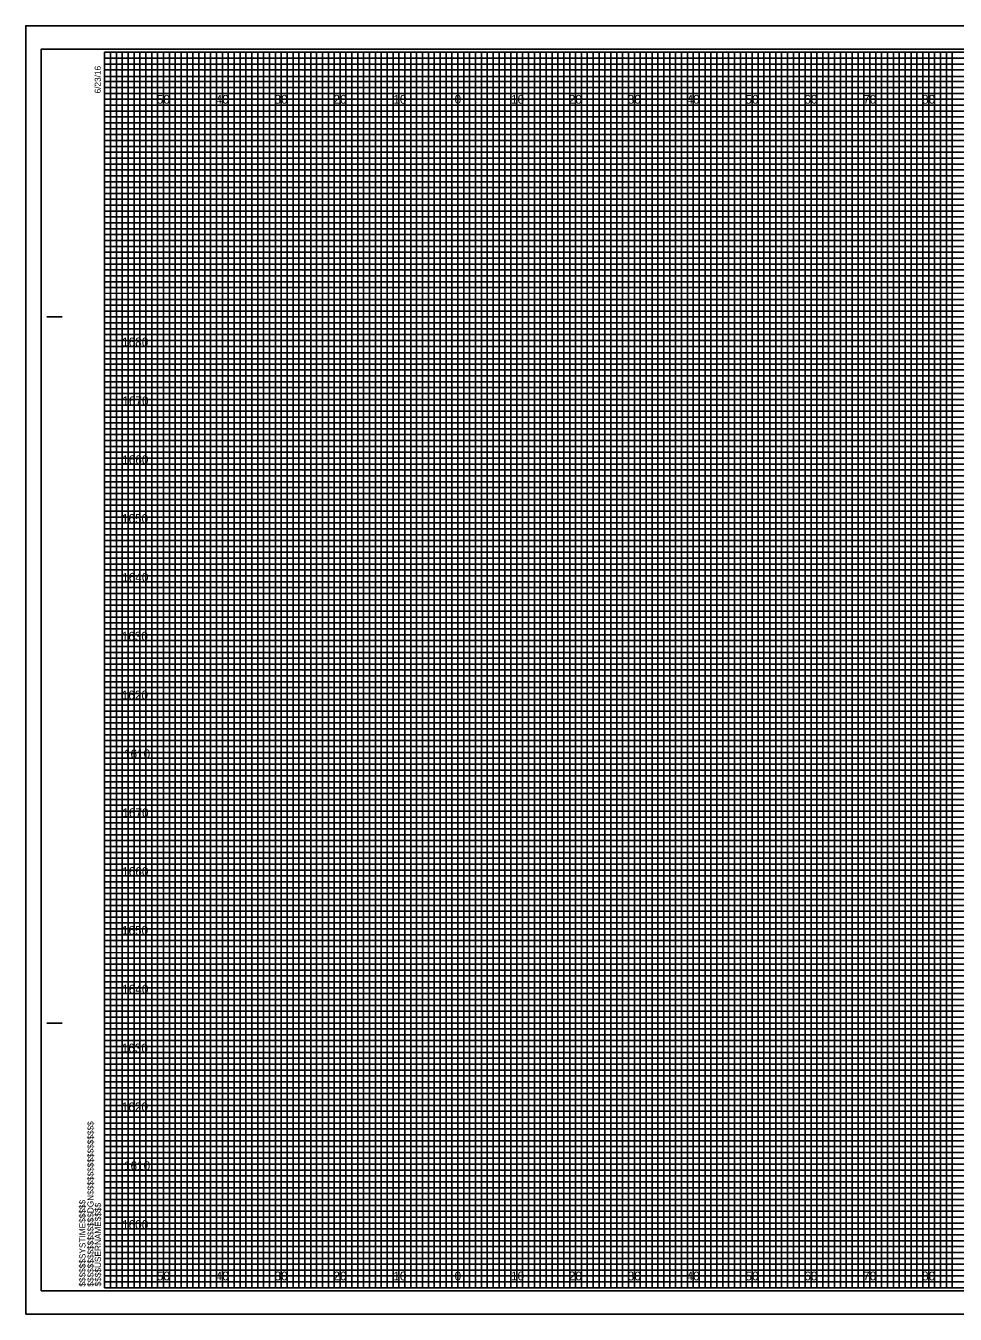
# Model space of a CAD drawing. Extents: x -13 to 323, y -5 to 6154.
# Drawn here: x -13.4 to 144.5, y 4395.5 to 4614.5 of the extents above; entities that cross this region are included whole.
import ezdxf

# ---------------------------------------------------------------- set-up
doc = ezdxf.new("R2010")
doc.units = 0
for name, color, linetype in [('Prop Retaining Wall', 7, 'Continuous'), ('Prop XS Alignment Label', 7, 'Continuous'), ('Prop XS DDE', 7, 'Continuous'), ('Prop XS DDE Elevations', 7, 'Continuous'), ('Prop XS DDE Slope Text', 7, 'Continuous'), ('Prop XS Earthwork Shape', 7, 'Continuous'), ('Prop XS Elevation Labels', 7, 'Continuous'), ('Prop XS Station Labels', 7, 'Continuous'), ('Raster_Level_0', 7, 'Continuous'), ('Scratch_Level_3', 7, 'Continuous'), ('Sheet Cutting Line CELL', 7, 'Continuous')]:
    doc.layers.add(name, color=color, linetype=linetype)

msp = doc.modelspace()

# ---------------------------------------------------------------- linework, layer by layer
at = {"layer": 'Prop Retaining Wall'}
for p, q in [((0, 4609), (260, 4609)), ((260, 4607.98), (0, 4607.98)), ((0, 4607.98), (0, 4607)), ((0, 4607), (260, 4607)), ((260, 4605.89), (0, 4605.89)), ((0, 4605.89), (0, 4604)), ((0, 4604), (320, 4604))]:
    msp.add_line(p, q, dxfattribs=at)
for points in [[(0, 4603), (270, 4603), (320, 4603), (320, 4602), (0, 4602)], [(0, 4601), (320, 4601), (320, 4599), (0, 4599)], [(0, 4598), (320, 4598), (320, 4597), (0, 4596.98)], [(0, 4596), (320, 4596), (320, 4594), (0, 4594)], [(0, 4593), (320, 4593), (320, 4592), (0, 4592)], [(0, 4591), (320, 4591), (320, 4589), (0, 4589)], [(0, 4588), (320, 4588), (320, 4587), (0, 4587)], [(0, 4586), (320, 4586), (320, 4584), (0, 4584)], [(0, 4583), (320, 4583), (320, 4582), (0, 4582)], [(0, 4581), (320, 4581), (320, 4579), (0, 4579)], [(0, 4578), (320, 4578), (320, 4577), (0, 4577)], [(0, 4576), (320, 4576), (320, 4573.95), (320, 4573), (320, 4572), (0, 4572)], [(0, 4574), (320, 4574), (320, 4573), (0, 4573)], [(0, 4571), (320, 4571), (320, 4569), (0, 4569.03)], [(0, 4569.03), (320, 4569), (320, 4568), (0, 4568)], [(0, 4567), (320, 4567), (320, 4566), (0, 4566)], [(0, 4564), (320, 4564), (320, 4563), (0, 4563)], [(0, 4562), (320, 4562), (320, 4561), (0, 4561)], [(-0.07, 4558.89), (320, 4558.89), (320, 4557.88), (-0.07, 4557.88)], [(0, 4557), (320, 4557), (320, 4556), (0, 4556)], [(0, 4554), (320, 4554), (320, 4553), (0, 4553)], [(0, 4552), (320, 4552), (320, 4551), (0, 4551)], [(0, 4549), (320, 4549), (320, 4548), (0, 4548)], [(0, 4547), (320, 4547), (320, 4546), (0, 4546)], [(0, 4544), (320, 4544), (320, 4543), (0, 4543)], [(0, 4542), (320, 4542), (320, 4541), (0, 4541)], [(0, 4539), (320, 4539), (319.99, 4537.98), (0, 4538)], [(0, 4537), (320, 4537), (320, 4536), (0, 4536)], [(0, 4534), (320, 4534), (320, 4533), (0, 4533)], [(0, 4532), (320, 4532), (320, 4531), (0, 4531)], [(0, 4529), (320, 4529), (320, 4528), (0, 4528)], [(0, 4527), (320, 4527), (320, 4526), (0, 4526)], [(0, 4524), (320, 4524), (320, 4523), (0, 4523)], [(0, 4522), (320, 4522), (320, 4521), (0, 4521)], [(0, 4519), (320, 4519), (320, 4518), (0, 4518)], [(0, 4516.99), (320.07, 4516.91), (320, 4516), (0, 4516)], [(0, 4514), (320, 4514), (320, 4513), (0, 4513)], [(0, 4512), (320, 4512), (320, 4511), (0, 4511)], [(0, 4509), (320, 4509), (320, 4508), (0, 4508)], [(0, 4507), (320, 4507), (320, 4506), (0, 4506)], [(0, 4504), (320, 4504), (320, 4503), (0, 4503)], [(0, 4502), (320, 4502), (320, 4501), (0, 4501)], [(0, 4499), (320, 4499), (320, 4498), (0, 4498)], [(0, 4497), (320, 4497), (320, 4496), (0, 4496)], [(0, 4494), (320, 4494), (320, 4493), (0, 4493)], [(0, 4492), (320, 4492), (320, 4491), (0, 4491)], [(0, 4489), (320, 4489), (320, 4488), (0, 4488)], [(0, 4487), (320, 4487), (320, 4486), (0, 4486)], [(0, 4484), (320, 4484), (320, 4483), (0, 4483)], [(0, 4482), (320, 4482), (320, 4481), (0, 4481)], [(0, 4479), (320, 4479), (319.99, 4477.98), (0, 4478)], [(0, 4477), (320, 4477), (320, 4476), (0, 4476)], [(0, 4474), (320, 4474), (320, 4473), (0, 4473)], [(0, 4472), (320, 4472), (320, 4471), (0, 4471)], [(0, 4469), (320, 4469), (320, 4468), (0, 4468)], [(0, 4467), (320, 4467), (320, 4466), (0, 4466)], [(0, 4464), (320, 4464), (320, 4463), (0, 4463)], [(0, 4462), (320, 4462), (320, 4461), (0, 4461)], [(0, 4459), (320, 4459), (320, 4458), (0, 4458)], [(0, 4456.99), (320.07, 4456.91), (320, 4456), (0, 4456)], [(0, 4454), (320, 4454), (320, 4453), (0, 4453)], [(0, 4452), (320, 4452), (320, 4451), (0, 4451)], [(0, 4449), (320, 4449), (320, 4448), (0, 4448)], [(0, 4447), (320, 4447), (320, 4446), (0, 4446)], [(0, 4444), (320, 4444), (320, 4443), (0, 4443)], [(0, 4442), (320, 4442), (320, 4441), (0, 4441)], [(0, 4439), (320, 4439), (320, 4438), (0, 4438)], [(0, 4437), (320, 4437), (320, 4436), (0, 4436)], [(0, 4434), (320, 4434), (320, 4433), (0, 4433)], [(0, 4432), (320, 4432), (320, 4431), (0, 4431)], [(0, 4429), (320, 4429), (320, 4428), (0, 4428)], [(0, 4427), (320, 4427), (320, 4426), (0, 4426)], [(0, 4424), (320, 4424), (320, 4423), (0, 4423)], [(0, 4422), (320, 4422), (320, 4421), (0, 4421)], [(0, 4419), (320, 4419), (320, 4418), (0, 4418)], [(0, 4417), (320, 4417), (320, 4416), (0, 4416)], [(0, 4414), (320, 4414), (320, 4413), (0, 4413)], [(0, 4412), (320, 4412), (320, 4411), (0, 4411)], [(0, 4409), (320, 4409), (320, 4408), (0, 4408)], [(0, 4407), (320, 4407), (320, 4406), (0, 4406)], [(0, 4404), (320, 4404), (320, 4403), (0, 4403)], [(0, 4402), (320, 4402), (320, 4401), (0, 4401)]]:
    msp.add_lwpolyline(points, dxfattribs=at)
at = {"layer": 'Prop XS Alignment Label'}
for p, q in [((-9.8, 4565), (-7.3, 4565)), ((-9.7, 4565), (-7.2, 4565)), ((-9.8, 4445), (-7.3, 4445)), ((-9.7, 4445), (-7.2, 4445)), ((0, 4400), (0, 4400)), ((0, 4400), (0, 4400)), ((0, 4400), (0, 4400)), ((0, 4400), (0, 4400)), ((0, 4400), (0, 4400)), ((0, 4400), (0, 4400)), ((0, 4400), (0, 4400))]:
    msp.add_line(p, q, dxfattribs=at)
msp.add_lwpolyline([(320, 4610), (0, 4610), (0, 4400), (320, 4400)], close=True, dxfattribs=at)
at = {"layer": 'Prop XS DDE'}
msp.add_lwpolyline([(-13.4, 4395.5), (323.3, 4395.5), (323.3, 4614.5), (-13.4, 4614.5)], close=True, dxfattribs=at)
at = {"layer": 'Prop XS DDE Elevations'}
for p, q in [((10, 4400), (10, 4610)), ((20, 4400), (20, 4610)), ((30, 4400), (30, 4610)), ((40, 4400), (40, 4610)), ((50, 4400), (50, 4610)), ((60, 4400), (60, 4610)), ((70, 4400), (70, 4610)), ((80, 4400), (80, 4610)), ((90, 4400), (90, 4610)), ((100, 4400), (100, 4610)), ((110, 4400), (110, 4610)), ((120, 4400), (120, 4610)), ((130, 4400), (130, 4610)), ((140, 4400), (140, 4610)), ((0, 4600), (320, 4600)), ((0, 4590), (320, 4590)), ((0, 4580), (320, 4580)), ((0, 4570), (320, 4570)), ((0, 4560), (320, 4560)), ((0, 4550), (320, 4550)), ((0, 4540), (320, 4540)), ((0, 4530), (320, 4530)), ((0, 4520), (320, 4520)), ((0, 4510), (320, 4510)), ((0, 4500), (320, 4500)), ((0, 4490), (320, 4490)), ((0, 4480), (320, 4480)), ((0, 4470), (320, 4470)), ((0, 4460), (320, 4460)), ((0, 4450), (320, 4450)), ((0, 4440), (320, 4440)), ((0, 4430), (320, 4430)), ((0, 4420), (320, 4420)), ((0, 4410), (320, 4410))]:
    msp.add_line(p, q, dxfattribs=at)
at = {"layer": 'Prop XS DDE Slope Text'}
msp.add_lwpolyline([(-10.8, 4399.5), (322.4, 4399.5), (322.4, 4610.5), (-10.8, 4610.5)], close=True, dxfattribs=at)
at = {"layer": 'Prop XS Earthwork Shape'}
for p, q in [((10, 4610), (0, 4610)), ((10, 4400), (10, 4610)), ((30, 4610), (20, 4610)), ((20, 4610), (20, 4400)), ((30, 4400), (30, 4610)), ((50, 4610), (40, 4610)), ((40, 4610), (40, 4400)), ((50, 4400), (50, 4610)), ((70, 4610), (60, 4610)), ((60, 4610), (60, 4400)), ((70, 4400), (70, 4610)), ((90, 4610), (80, 4610)), ((80, 4610), (80, 4400)), ((90, 4400), (90, 4610)), ((110, 4610), (100, 4610)), ((100, 4610), (100, 4400)), ((110, 4400), (110, 4610)), ((130, 4610), (120, 4610)), ((120, 4610), (120, 4400)), ((130, 4400), (130, 4610)), ((150, 4610), (140, 4610)), ((140, 4610), (140, 4400)), ((20, 4400), (10, 4400)), ((40, 4400), (30, 4400)), ((60, 4400), (50, 4400)), ((80, 4400), (70, 4400)), ((100, 4400), (90, 4400)), ((120, 4400), (110, 4400)), ((140, 4400), (130, 4400))]:
    msp.add_line(p, q, dxfattribs=at)
for points in [[(0, 4600), (320, 4600), (320, 4590), (0, 4590)], [(0, 4580), (320, 4580), (320, 4570), (0, 4570)], [(0, 4560), (320, 4560), (320, 4550), (0, 4550)], [(0, 4540), (320, 4540), (320, 4530), (0, 4530)], [(0, 4520), (320, 4520), (320, 4510), (0, 4510)], [(0, 4500), (320, 4500), (320, 4490), (0, 4490)], [(0, 4480), (320, 4480), (320, 4470), (0, 4470)], [(0, 4460), (320, 4460), (320, 4450), (0, 4450)], [(0, 4440), (320, 4440), (320, 4430), (0, 4430)], [(0, 4420), (320, 4420), (320, 4410), (0, 4410)]]:
    msp.add_lwpolyline(points, dxfattribs=at)
at = {"layer": 'Prop XS Elevation Labels'}
for points in [[(0, 4400), (1, 4400), (1, 4610), (2, 4610), (2, 4400)], [(2, 4400), (3, 4400), (3, 4610), (4, 4610), (4, 4400)], [(5, 4400), (6, 4400), (6, 4610), (7, 4610), (7, 4400)], [(7, 4400), (8, 4400), (8, 4610), (9, 4610), (9, 4400)], [(10, 4400), (11, 4400), (11, 4610), (12, 4610), (12, 4400)], [(12, 4400), (13, 4400), (13, 4610), (14, 4610), (14, 4400)], [(15, 4400), (16, 4400), (16, 4610), (17, 4610), (17, 4400)], [(17, 4400), (18, 4400), (18, 4610), (19, 4610), (19, 4400)], [(20, 4400), (21, 4400), (21, 4610), (22, 4610), (22, 4400)], [(22, 4400), (23, 4400), (23, 4610), (24, 4610), (24, 4400)], [(25, 4400), (26, 4400), (26, 4610), (27, 4610), (27, 4400)], [(27, 4400), (28, 4400), (28, 4610), (29, 4610), (29, 4400)], [(30, 4400), (31, 4400), (31, 4610), (32, 4610), (32, 4400)], [(32, 4400), (33, 4400), (33, 4610), (34, 4610), (34, 4400)], [(35, 4400), (36, 4400), (36, 4610), (37, 4610), (37, 4400)], [(37, 4400), (38, 4400), (38, 4610), (39, 4610), (39, 4400)], [(40, 4400), (41, 4400), (41, 4610), (42, 4610), (42, 4400)], [(42, 4400), (43, 4400), (43, 4610), (44, 4610), (44, 4400)], [(45, 4400), (46, 4400), (46, 4610), (47, 4610), (47, 4400)], [(47, 4400), (48, 4400), (48, 4610), (49, 4610), (49, 4400)], [(50, 4400), (51, 4400), (51, 4610), (52, 4610), (52, 4400)], [(52, 4400), (53, 4400), (53, 4610), (54, 4610), (54, 4400)], [(55, 4400), (56, 4400), (56, 4610), (57, 4610), (57, 4400)], [(57, 4400), (58, 4400), (58, 4610), (59, 4610), (59, 4400)], [(60, 4400), (61, 4400), (61, 4610), (62, 4610), (62, 4400)], [(62, 4400), (63, 4400), (63, 4610), (64, 4610), (64, 4400)], [(65, 4400), (66, 4400), (66, 4610), (67, 4610), (67, 4400)], [(67, 4400), (68, 4400), (68, 4610), (69, 4610), (69, 4400)], [(70, 4400), (71, 4400), (71, 4610), (72, 4610), (72, 4400)], [(72, 4400), (73, 4400), (73, 4610), (74, 4610), (74, 4400)], [(75, 4400), (76, 4400), (76, 4610), (77, 4610), (77, 4400)], [(77, 4400), (78, 4400), (78, 4610), (79, 4610), (79, 4400)], [(80, 4400), (81, 4400), (81, 4610), (82, 4610), (82, 4400)], [(82, 4400), (83, 4400), (83, 4610), (84, 4610), (84, 4400)], [(85, 4400), (86, 4400), (86, 4610), (87, 4610), (87, 4400)], [(87, 4400), (88, 4400), (88, 4610), (89, 4610), (89, 4400)], [(90, 4400), (91, 4400), (91, 4610), (92, 4610), (92, 4400)], [(92, 4400), (93, 4400), (93, 4610), (94, 4610), (94, 4400)], [(95, 4400), (96, 4400), (96, 4610), (97, 4610), (97, 4400)], [(97, 4400), (98, 4400), (98, 4610), (99, 4610), (99, 4400)], [(100, 4400), (101, 4400), (101, 4610), (102, 4610), (102, 4400)], [(102, 4400), (103, 4400), (103, 4610), (104, 4610), (104, 4400)], [(105, 4400), (106, 4400), (106, 4610), (107, 4610), (107, 4400)], [(107, 4400), (108, 4400), (108, 4610), (109, 4610), (109, 4400)], [(110, 4400), (111, 4400), (111, 4610), (112, 4610), (112, 4400)], [(112, 4400), (113, 4400), (113, 4610), (114, 4610), (114, 4400)], [(115, 4400), (116, 4400), (116, 4610), (117, 4610), (117, 4400)], [(117, 4400), (118, 4400), (118, 4610), (119, 4610), (119, 4400)], [(120, 4400), (121, 4400), (121, 4610), (122, 4610), (122, 4400)], [(122, 4400), (123, 4400), (123, 4610), (124, 4610), (124, 4400)], [(125, 4400), (126, 4400), (126, 4610), (127, 4610), (127, 4400)], [(127, 4400), (128, 4400), (128, 4610), (129, 4610), (129, 4400)], [(130, 4400), (131, 4400), (131, 4610), (132, 4610), (132, 4400)], [(132, 4400), (133, 4400), (133, 4610), (134, 4610), (134, 4400)], [(135, 4400), (136, 4400), (136, 4610), (137, 4610), (137, 4400)], [(137, 4400), (138, 4400), (138, 4610), (139, 4610), (139, 4400)], [(140, 4400), (141, 4400), (141, 4610), (142, 4610), (142, 4400)], [(142, 4400), (143, 4400), (143, 4610), (144, 4610), (144, 4400)]]:
    msp.add_lwpolyline(points, dxfattribs=at)
at = {"layer": 'Prop XS Station Labels'}
for points in [[(0, 4610), (5, 4610), (5, 4400), (15, 4400), (15, 4610), (25, 4610), (25, 4400), (35, 4400), (35, 4610), (45, 4610), (45, 4400), (55, 4400), (55, 4610), (65, 4610), (65, 4400), (75, 4400), (75, 4610), (85, 4610), (85, 4400), (95, 4400), (95, 4610), (105, 4610), (105, 4400), (115, 4400), (115, 4610), (125, 4610), (125, 4400), (135, 4400), (135, 4610), (145, 4610)], [(0, 4605), (275, 4605)], [(0, 4585), (320, 4585), (320, 4595), (0, 4595)], [(0, 4565), (320, 4565), (320, 4575), (0, 4575)], [(0, 4545), (320, 4545), (320, 4555), (0, 4555)], [(0, 4525), (320, 4525), (320, 4535), (0, 4535)], [(0, 4505), (320, 4505), (320, 4515), (0, 4515)], [(0, 4485), (320, 4485), (320, 4495), (0, 4495)], [(0, 4465), (320, 4465), (320, 4475), (0, 4475)], [(0, 4445), (320, 4445), (320, 4455), (0, 4455)], [(0, 4425), (320, 4425), (320, 4435), (0, 4435)], [(0, 4405), (320, 4405), (320, 4415), (0, 4415)]]:
    msp.add_lwpolyline(points, dxfattribs=at)
at = {"layer": 'Sheet Cutting Line CELL'}
for p, q in [((323.3, 4614.5), (-13.4, 4614.5)), ((-13.4, 4614.5), (-13.4, 4395.5)), ((-13.4, 4395.5), (323.3, 4395.5))]:
    msp.add_line(p, q, dxfattribs=at)

# ---------------------------------------------------------------- texts
at = {"layer": 'Prop XS Alignment Label'}
for s, p in [('6/23/16', (-0.65, 4603)), ('$$$$$$$$$$$$$$$$DGN$$$$$$$$$$$$$$$$', (-1.88, 4400.18)), ('$$$$$$SYSTIME$$$$$', (-3.26, 4400.18)), ('$$$$USERNAME$$$$', (-0.62, 4400.23))]:
    msp.add_text(s, height=1.05, rotation=90, dxfattribs=at).set_placement(p)
at = {"layer": 'Raster_Level_0'}
for s, p in [('50', (8.86, 4601.25)), ('40', (18.86, 4601.25)), ('30', (28.86, 4601.25)), ('20', (38.86, 4601.25)), ('10', (49.04, 4601.25)), ('0', (59.45, 4601.25)), ('0', (59.45, 4601.25)), ('10', (69.04, 4601.25)), ('20', (78.86, 4601.25)), ('30', (88.86, 4601.25)), ('40', (98.86, 4601.25)), ('50', (108.86, 4601.25)), ('60', (118.86, 4601.25)), ('70', (128.86, 4601.25)), ('80', (138.86, 4601.25)), ('50', (8.86, 4401.25)), ('40', (18.86, 4401.25)), ('30', (28.86, 4401.25)), ('20', (38.86, 4401.25)), ('10', (49.04, 4401.25)), ('0', (59.45, 4401.25)), ('0', (59.45, 4401.25)), ('10', (69.04, 4401.25)), ('20', (78.86, 4401.25)), ('30', (88.86, 4401.25)), ('40', (98.86, 4401.25)), ('50', (108.86, 4401.25)), ('60', (118.86, 4401.25)), ('70', (128.86, 4401.25)), ('80', (138.86, 4401.25))]:
    msp.add_text(s, height=1.5, dxfattribs=at).set_placement(p)
at = {"layer": 'Scratch_Level_3'}
for s, p in [('1680', (2.95, 4560)), ('1670', (3, 4550)), ('1660', (2.97, 4540)), ('1650', (2.92, 4530)), ('1640', (2.97, 4520)), ('1630', (2.89, 4510)), ('1620', (2.9, 4500)), ('1610', (3.28, 4490)), ('1670', (3, 4480)), ('1660', (2.97, 4470)), ('1650', (2.92, 4460)), ('1640', (2.97, 4450)), ('1630', (2.89, 4440)), ('1620', (2.9, 4430)), ('1610', (3.28, 4420)), ('1600', (2.95, 4410))]:
    msp.add_text(s, height=1.5, dxfattribs=at).set_placement(p)

doc.saveas('drawing.dxf')
